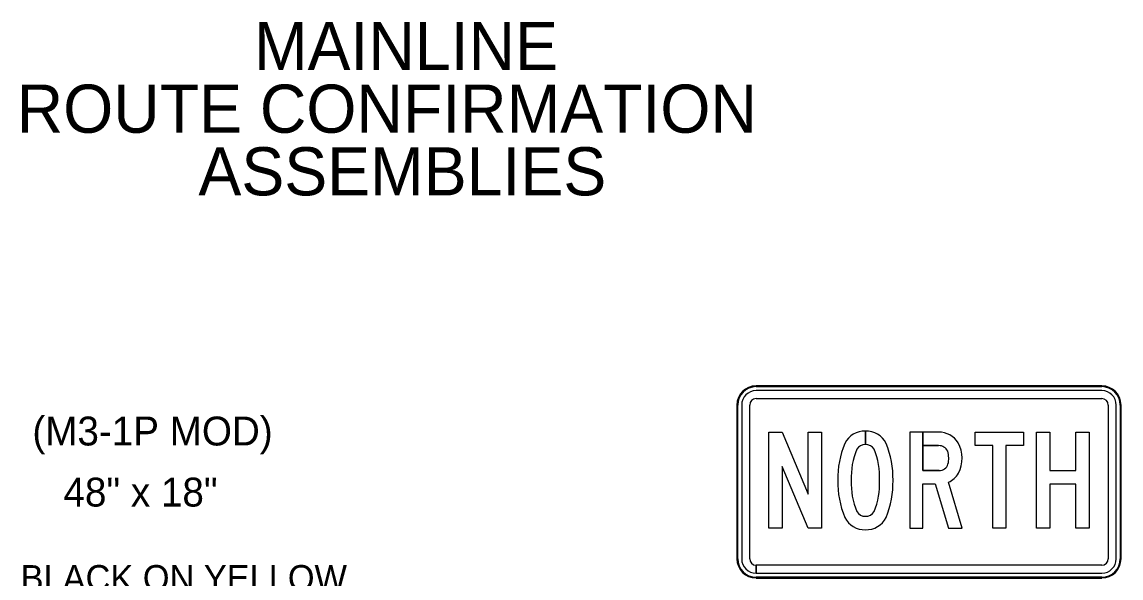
# Model space of a CAD drawing. Extents: x 17890587 to 17890754, y 17897693 to 17897992.
# Drawn here: x 17890592.3 to 17890600.01, y 17897885.1 to 17897888.99 of the extents above; entities that cross this region are included whole.
import ezdxf

# ---------------------------------------------------------------- set-up
doc = ezdxf.new("R2010")
doc.units = 0
doc.layers.add('GSColorFill', color=7, linetype='Continuous')
doc.layers.add('TextMisc', color=7, linetype='Continuous')

msp = doc.modelspace()

# ---------------------------------------------------------------- linework, layer by layer
at = {"layer": 'GSColorFill'}
for p, q in [((17890599.8718, 17897886.4444), (17890597.4481, 17897886.4444)), ((17890599.8718, 17897886.4444), (17890597.4481, 17897886.4444)), ((17890597.4481, 17897886.4388), (17890599.8718, 17897886.4388)), ((17890599.8718, 17897886.4108), (17890597.4481, 17897886.4108)), ((17890597.4481, 17897886.3547), (17890599.8718, 17897886.3547)), ((17890597.3135, 17897886.3098), (17890597.3135, 17897885.2326)), ((17890597.3135, 17897886.3098), (17890597.3135, 17897885.2326)), ((17890597.3191, 17897885.2326), (17890597.3191, 17897886.3098)), ((17890597.3471, 17897886.3098), (17890597.3471, 17897885.2326)), ((17890597.4032, 17897885.2326), (17890597.4032, 17897886.3098)), ((17890599.9167, 17897886.3098), (17890599.9167, 17897885.2326)), ((17890599.9728, 17897885.2326), (17890599.9728, 17897886.3098)), ((17890600.0008, 17897886.3098), (17890600.0008, 17897885.2326)), ((17890600.0065, 17897885.2326), (17890600.0065, 17897886.3098)), ((17890600.0065, 17897885.2326), (17890600.0065, 17897886.3098)), ((17890598.2146, 17897886.0329), (17890598.2146, 17897886.1277)), ((17890598.2146, 17897886.1277), (17890598.2146, 17897886.0329)), ((17890598.2146, 17897886.0329), (17890598.2146, 17897886.1277)), ((17890598.2146, 17897886.1277), (17890598.2146, 17897886.0329)), ((17890598.893, 17897885.4463), (17890598.7971, 17897885.7693)), ((17890597.4481, 17897885.1316), (17890597.4481, 17897885.1877)), ((17890599.8718, 17897885.1877), (17890597.4487, 17897885.1877)), ((17890597.4487, 17897885.1877), (17890597.4487, 17897885.1316)), ((17890597.4481, 17897885.0979), (17890597.4481, 17897885.1035)), ((17890597.4481, 17897885.0979), (17890599.8718, 17897885.0979)), ((17890599.8718, 17897885.1035), (17890597.4482, 17897885.1035)), ((17890597.4482, 17897885.1035), (17890597.4482, 17897885.0979)), ((17890597.4482, 17897885.0979), (17890599.8718, 17897885.0979)), ((17890597.4487, 17897885.1316), (17890599.8718, 17897885.1316))]:
    msp.add_line(p, q, dxfattribs=at)
for points in [[(17890597.6304, 17897886.1195), (17890597.8131, 17897885.6858), (17890597.8131, 17897886.1195), (17890597.9059, 17897886.1195), (17890597.9059, 17897885.4463), (17890597.8131, 17897885.4463), (17890597.6307, 17897885.8789), (17890597.6307, 17897885.4463), (17890597.5379, 17897885.4463), (17890597.5379, 17897886.1195)], [(17890597.6304, 17897886.1195), (17890597.8131, 17897885.6858), (17890597.8131, 17897886.1195), (17890597.9059, 17897886.1195), (17890597.9059, 17897885.4463), (17890597.8131, 17897885.4463), (17890597.6307, 17897885.8789), (17890597.6307, 17897885.4463), (17890597.5379, 17897885.4463), (17890597.5379, 17897886.1195)], [(17890597.6304, 17897886.1195), (17890597.8131, 17897885.6858), (17890597.8131, 17897886.1195), (17890597.9059, 17897886.1195), (17890597.9059, 17897885.4463), (17890597.8131, 17897885.4463), (17890597.6307, 17897885.8789), (17890597.6307, 17897885.4463), (17890597.5379, 17897885.4463), (17890597.5379, 17897886.1195)], [(17890599.1071, 17897886.0252), (17890598.9845, 17897886.0252), (17890598.9845, 17897886.1195), (17890599.3227, 17897886.1195), (17890599.3227, 17897886.0252), (17890599.1999, 17897886.0252), (17890599.1999, 17897885.4463), (17890599.1071, 17897885.4463)], [(17890599.1071, 17897886.0252), (17890598.9845, 17897886.0252), (17890598.9845, 17897886.1195), (17890599.3227, 17897886.1195), (17890599.3227, 17897886.0252), (17890599.1999, 17897886.0252), (17890599.1999, 17897885.4463), (17890599.1071, 17897885.4463)], [(17890599.1071, 17897886.0252), (17890598.9845, 17897886.0252), (17890598.9845, 17897886.1195), (17890599.3227, 17897886.1195), (17890599.3227, 17897886.0252), (17890599.1999, 17897886.0252), (17890599.1999, 17897885.4463), (17890599.1071, 17897885.4463)], [(17890599.414, 17897886.1195), (17890599.5068, 17897886.1195), (17890599.5068, 17897885.8502), (17890599.6892, 17897885.8502), (17890599.6892, 17897886.1195), (17890599.782, 17897886.1195), (17890599.782, 17897885.4463), (17890599.6892, 17897885.4463), (17890599.6892, 17897885.7559), (17890599.5068, 17897885.7559), (17890599.5068, 17897885.4463), (17890599.414, 17897885.4463)], [(17890599.414, 17897886.1195), (17890599.5068, 17897886.1195), (17890599.5068, 17897885.8502), (17890599.6892, 17897885.8502), (17890599.6892, 17897886.1195), (17890599.782, 17897886.1195), (17890599.782, 17897885.4463), (17890599.6892, 17897885.4463), (17890599.6892, 17897885.7559), (17890599.5068, 17897885.7559), (17890599.5068, 17897885.4463), (17890599.414, 17897885.4463)], [(17890599.414, 17897886.1195), (17890599.5068, 17897886.1195), (17890599.5068, 17897885.8502), (17890599.6892, 17897885.8502), (17890599.6892, 17897886.1195), (17890599.782, 17897886.1195), (17890599.782, 17897885.4463), (17890599.6892, 17897885.4463), (17890599.6892, 17897885.7559), (17890599.5068, 17897885.7559), (17890599.5068, 17897885.4463), (17890599.414, 17897885.4463)]]:
    msp.add_lwpolyline(points, close=True, dxfattribs=at)
for points in [[(17890598.7277, 17897886.1195), (17890598.525, 17897886.1195), (17890598.525, 17897885.4463), (17890598.6179, 17897885.4463), (17890598.6179, 17897885.758), (17890598.7035, 17897885.758), (17890598.7961, 17897885.4463), (17890598.893, 17897885.4463)], [(17890598.7312, 17897885.8522), (17890598.6179, 17897885.8522), (17890598.6179, 17897886.1195), (17890598.525, 17897886.1195), (17890598.525, 17897885.4463)], [(17890598.7312, 17897885.8522), (17890598.6179, 17897885.8522), (17890598.6179, 17897886.1195), (17890598.525, 17897886.1195), (17890598.525, 17897885.4463)], [(17890598.7277, 17897886.1195), (17890598.6179, 17897886.1195), (17890598.6179, 17897886.0252), (17890598.7277, 17897886.0252)], [(17890598.7277, 17897886.1195), (17890598.6179, 17897886.1195), (17890598.6179, 17897886.0252), (17890598.7277, 17897886.0252)], [(17890598.7277, 17897886.0252), (17890598.6179, 17897886.0252), (17890598.6179, 17897885.8522), (17890598.7312, 17897885.8522)], [(17890598.525, 17897885.4463), (17890598.6179, 17897885.4463), (17890598.6179, 17897885.758), (17890598.7035, 17897885.758), (17890598.7961, 17897885.4463), (17890598.893, 17897885.4463), (17890598.7971, 17897885.7693)], [(17890598.525, 17897885.4463), (17890598.6179, 17897885.4463), (17890598.6179, 17897885.758), (17890598.7035, 17897885.758), (17890598.7961, 17897885.4463), (17890598.893, 17897885.4463), (17890598.7971, 17897885.7693)]]:
    msp.add_lwpolyline(points, dxfattribs=at)
for centre, radius, start, end in [((17890597.4481, 17897886.3098), 0.1346, 90, 180), ((17890597.4481, 17897886.3098), 0.1346, 90, 180), ((17890597.4481, 17897886.3098), 0.129, 90, 180), ((17890597.4481, 17897886.3098), 0.101, 90, 180), ((17890599.8718, 17897886.3098), 0.1346, 0, 90), ((17890599.8718, 17897886.3098), 0.1346, 0, 90), ((17890599.8718, 17897886.3098), 0.129, 0, 90), ((17890599.8718, 17897886.3098), 0.101, 0, 90), ((17890597.4481, 17897886.3098), 0.0449, 90, 180), ((17890599.8718, 17897886.3098), 0.0449, 0, 90), ((17890597.4481, 17897885.2326), 0.1346, 180, 270), ((17890597.4481, 17897885.2326), 0.1346, 180, 270), ((17890597.4481, 17897885.2326), 0.129, 180, 270), ((17890597.4481, 17897885.2326), 0.101, 180, 270), ((17890597.4481, 17897885.2326), 0.0449, 180, 270), ((17890599.8718, 17897885.2326), 0.1346, 270, 0), ((17890599.8718, 17897885.2326), 0.1346, 270, 0), ((17890599.8718, 17897885.2326), 0.129, 270, 0), ((17890599.8718, 17897885.2326), 0.101, 270, 0), ((17890599.8718, 17897885.2326), 0.0449, 270, 0)]:
    msp.add_arc(centre, radius, start, end, dxfattribs=at)
for centre, major_axis, start_param, end_param in [((17890598.2092, 17897885.9691), (0, 0.1586), 6.248265, 7.383959), ((17890598.2092, 17897885.9691), (0, 0.1586), 6.248265, 7.383959), ((17890598.2092, 17897885.9691), (0, 0.1586), 6.248265, 7.383959), ((17890598.2201, 17897885.9691), (0, 0.1586), 5.182411, 6.318105), ((17890598.2201, 17897885.9691), (0, 0.1586), 5.182411, 6.317893), ((17890598.2201, 17897885.9691), (0, 0.1586), 5.182411, 6.317893), ((17890598.731, 17897885.9577), (0, 0.1619), 5.284461, 6.303565), ((17890598.731, 17897885.9577), (0, 0.1619), 5.284461, 6.303565), ((17890598.731, 17897885.9577), (0, 0.1619), 5.284461, 6.303565), ((17890598.6499, 17897885.7944), (0, 0.6384), 1.174158, 1.59042), ((17890598.6499, 17897885.7944), (0, 0.6384), 1.174158, 1.59042), ((17890598.6499, 17897885.7944), (0, 0.6384), 1.174158, 1.59042), ((17890598.2111, 17897885.9652), (0, 0.0678), 6.22959, 7.30809), ((17890598.2111, 17897885.9652), (0, 0.0678), 6.22959, 7.30809), ((17890598.2111, 17897885.9652), (0, 0.0678), 6.22959, 7.30809), ((17890598.2182, 17897885.9652), (0, 0.0678), 5.258281, 6.33678), ((17890598.2182, 17897885.9652), (0, 0.0678), 5.258281, 6.336283), ((17890598.2182, 17897885.9652), (0, 0.0678), 5.258281, 6.336283), ((17890597.7794, 17897885.7944), (0, 0.6384), 4.692766, 5.109028), ((17890597.7794, 17897885.7944), (0, 0.6384), 4.692766, 5.109028), ((17890597.7794, 17897885.7944), (0, 0.6384), 4.692766, 5.109028), ((17890598.7301, 17897885.956), (0, 0.0693), 5.168949, 6.317293), ((17890598.7301, 17897885.956), (0, 0.0693), 5.168949, 6.317293), ((17890598.7301, 17897885.956), (0, 0.0693), 5.168949, 6.317293), ((17890598.6711, 17897885.9373), (0, 0.2246), 4.22428, 5.21411), ((17890598.6711, 17897885.9373), (0, 0.2246), 4.22428, 5.21411), ((17890598.6711, 17897885.9373), (0, 0.2246), 4.22428, 5.21411), ((17890598.6087, 17897885.8046), (0, 0.5014), 1.169623, 1.616135), ((17890598.6087, 17897885.8046), (0, 0.5014), 1.169623, 1.616135), ((17890598.6087, 17897885.8046), (0, 0.5014), 1.169623, 1.616135), ((17890597.8206, 17897885.8046), (0, 0.5014), 4.667051, 5.113562), ((17890597.8206, 17897885.8046), (0, 0.5014), 4.667051, 5.113562), ((17890597.8206, 17897885.8046), (0, 0.5014), 4.667051, 5.113562), ((17890598.6273, 17897885.9368), (0, 0.1738), 4.469957, 5.002454), ((17890598.6273, 17897885.9368), (0, 0.1738), 4.469957, 5.002454), ((17890598.6273, 17897885.9368), (0, 0.1738), 4.469957, 5.002454), ((17890598.7362, 17897885.9128), (0, 0.0608), 3.056737, 4.417555), ((17890598.7362, 17897885.9128), (0, 0.0608), 3.056737, 4.417555), ((17890598.7362, 17897885.9128), (0, 0.0608), 3.056737, 4.417555), ((17890598.6499, 17897885.7693), (0, 0.6384), 1.551173, 1.967435), ((17890598.6499, 17897885.7693), (0, 0.6384), 1.551173, 1.967435), ((17890598.6499, 17897885.7693), (0, 0.6384), 1.551173, 1.967435), ((17890598.6087, 17897885.7591), (0, 0.5014), 1.525458, 1.97197), ((17890598.6087, 17897885.7591), (0, 0.5014), 1.525458, 1.97197), ((17890598.6087, 17897885.7591), (0, 0.5014), 1.525458, 1.97197), ((17890597.8206, 17897885.7591), (0, 0.5014), 4.311216, 4.757727), ((17890597.8206, 17897885.7591), (0, 0.5014), 4.311216, 4.757727), ((17890597.8206, 17897885.7591), (0, 0.5014), 4.311216, 4.757727), ((17890597.7794, 17897885.7693), (0, 0.6384), 4.31575, 4.732012), ((17890597.7794, 17897885.7693), (0, 0.6384), 4.31575, 4.732012), ((17890597.7794, 17897885.7693), (0, 0.6384), 4.31575, 4.732012), ((17890598.7317, 17897885.9148), (0, 0.16), 3.569693, 4.167803), ((17890598.7317, 17897885.9148), (0, 0.16), 3.569693, 4.167803), ((17890598.7317, 17897885.9148), (0, 0.16), 3.569693, 4.167803), ((17890598.2111, 17897885.5985), (0, 0.0678), 2.116688, 3.195188), ((17890598.2111, 17897885.5985), (0, 0.0678), 2.116688, 3.195188), ((17890598.2111, 17897885.5985), (0, 0.0678), 2.116688, 3.195188), ((17890598.2182, 17897885.5985), (0, 0.0678), 3.087997, 4.166497), ((17890598.2182, 17897885.5985), (0, 0.0678), 3.087997, 4.166497), ((17890598.2182, 17897885.5985), (0, 0.0678), 3.087997, 4.166497), ((17890598.2092, 17897885.5945), (0, 0.1586), 2.040819, 3.176513), ((17890598.2092, 17897885.5945), (0, 0.1586), 2.040819, 3.176513), ((17890598.2092, 17897885.5945), (0, 0.1586), 2.040819, 3.176513), ((17890598.2201, 17897885.5945), (0, 0.1586), 3.106673, 4.242367), ((17890598.2201, 17897885.5945), (0, 0.1586), 3.106673, 4.242367), ((17890598.2201, 17897885.5945), (0, 0.1586), 3.106673, 4.242367)]:
    msp.add_ellipse(centre, major_axis=major_axis, ratio=0.985082, start_param=start_param, end_param=end_param, dxfattribs=at)

# ---------------------------------------------------------------- texts
at = {"layer": 'TextMisc'}
for s, height, p in [('MAINLINE ', 0.33745, (17890593.928, 17897888.6562)), ('ROUTE CONFIRMATION', 0.337451, (17890592.2648, 17897888.2175)), ('ASSEMBLIES', 0.33745, (17890593.5387, 17897887.7788)), ('(M3-1P MOD)', 0.202479, (17890592.3747, 17897886.0265)), ('48" x 18"', 0.20248, (17890592.5927, 17897885.5986)), ('BLACK ON YELLOW', 0.17999, (17890592.2927, 17897885.0087))]:
    msp.add_text(s, height=height, dxfattribs=at).set_placement(p)

doc.saveas('drawing.dxf')
